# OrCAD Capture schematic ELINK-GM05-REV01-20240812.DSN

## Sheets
1 02 SIM: size A3; title: Elink-GM05-REV01; note: Main
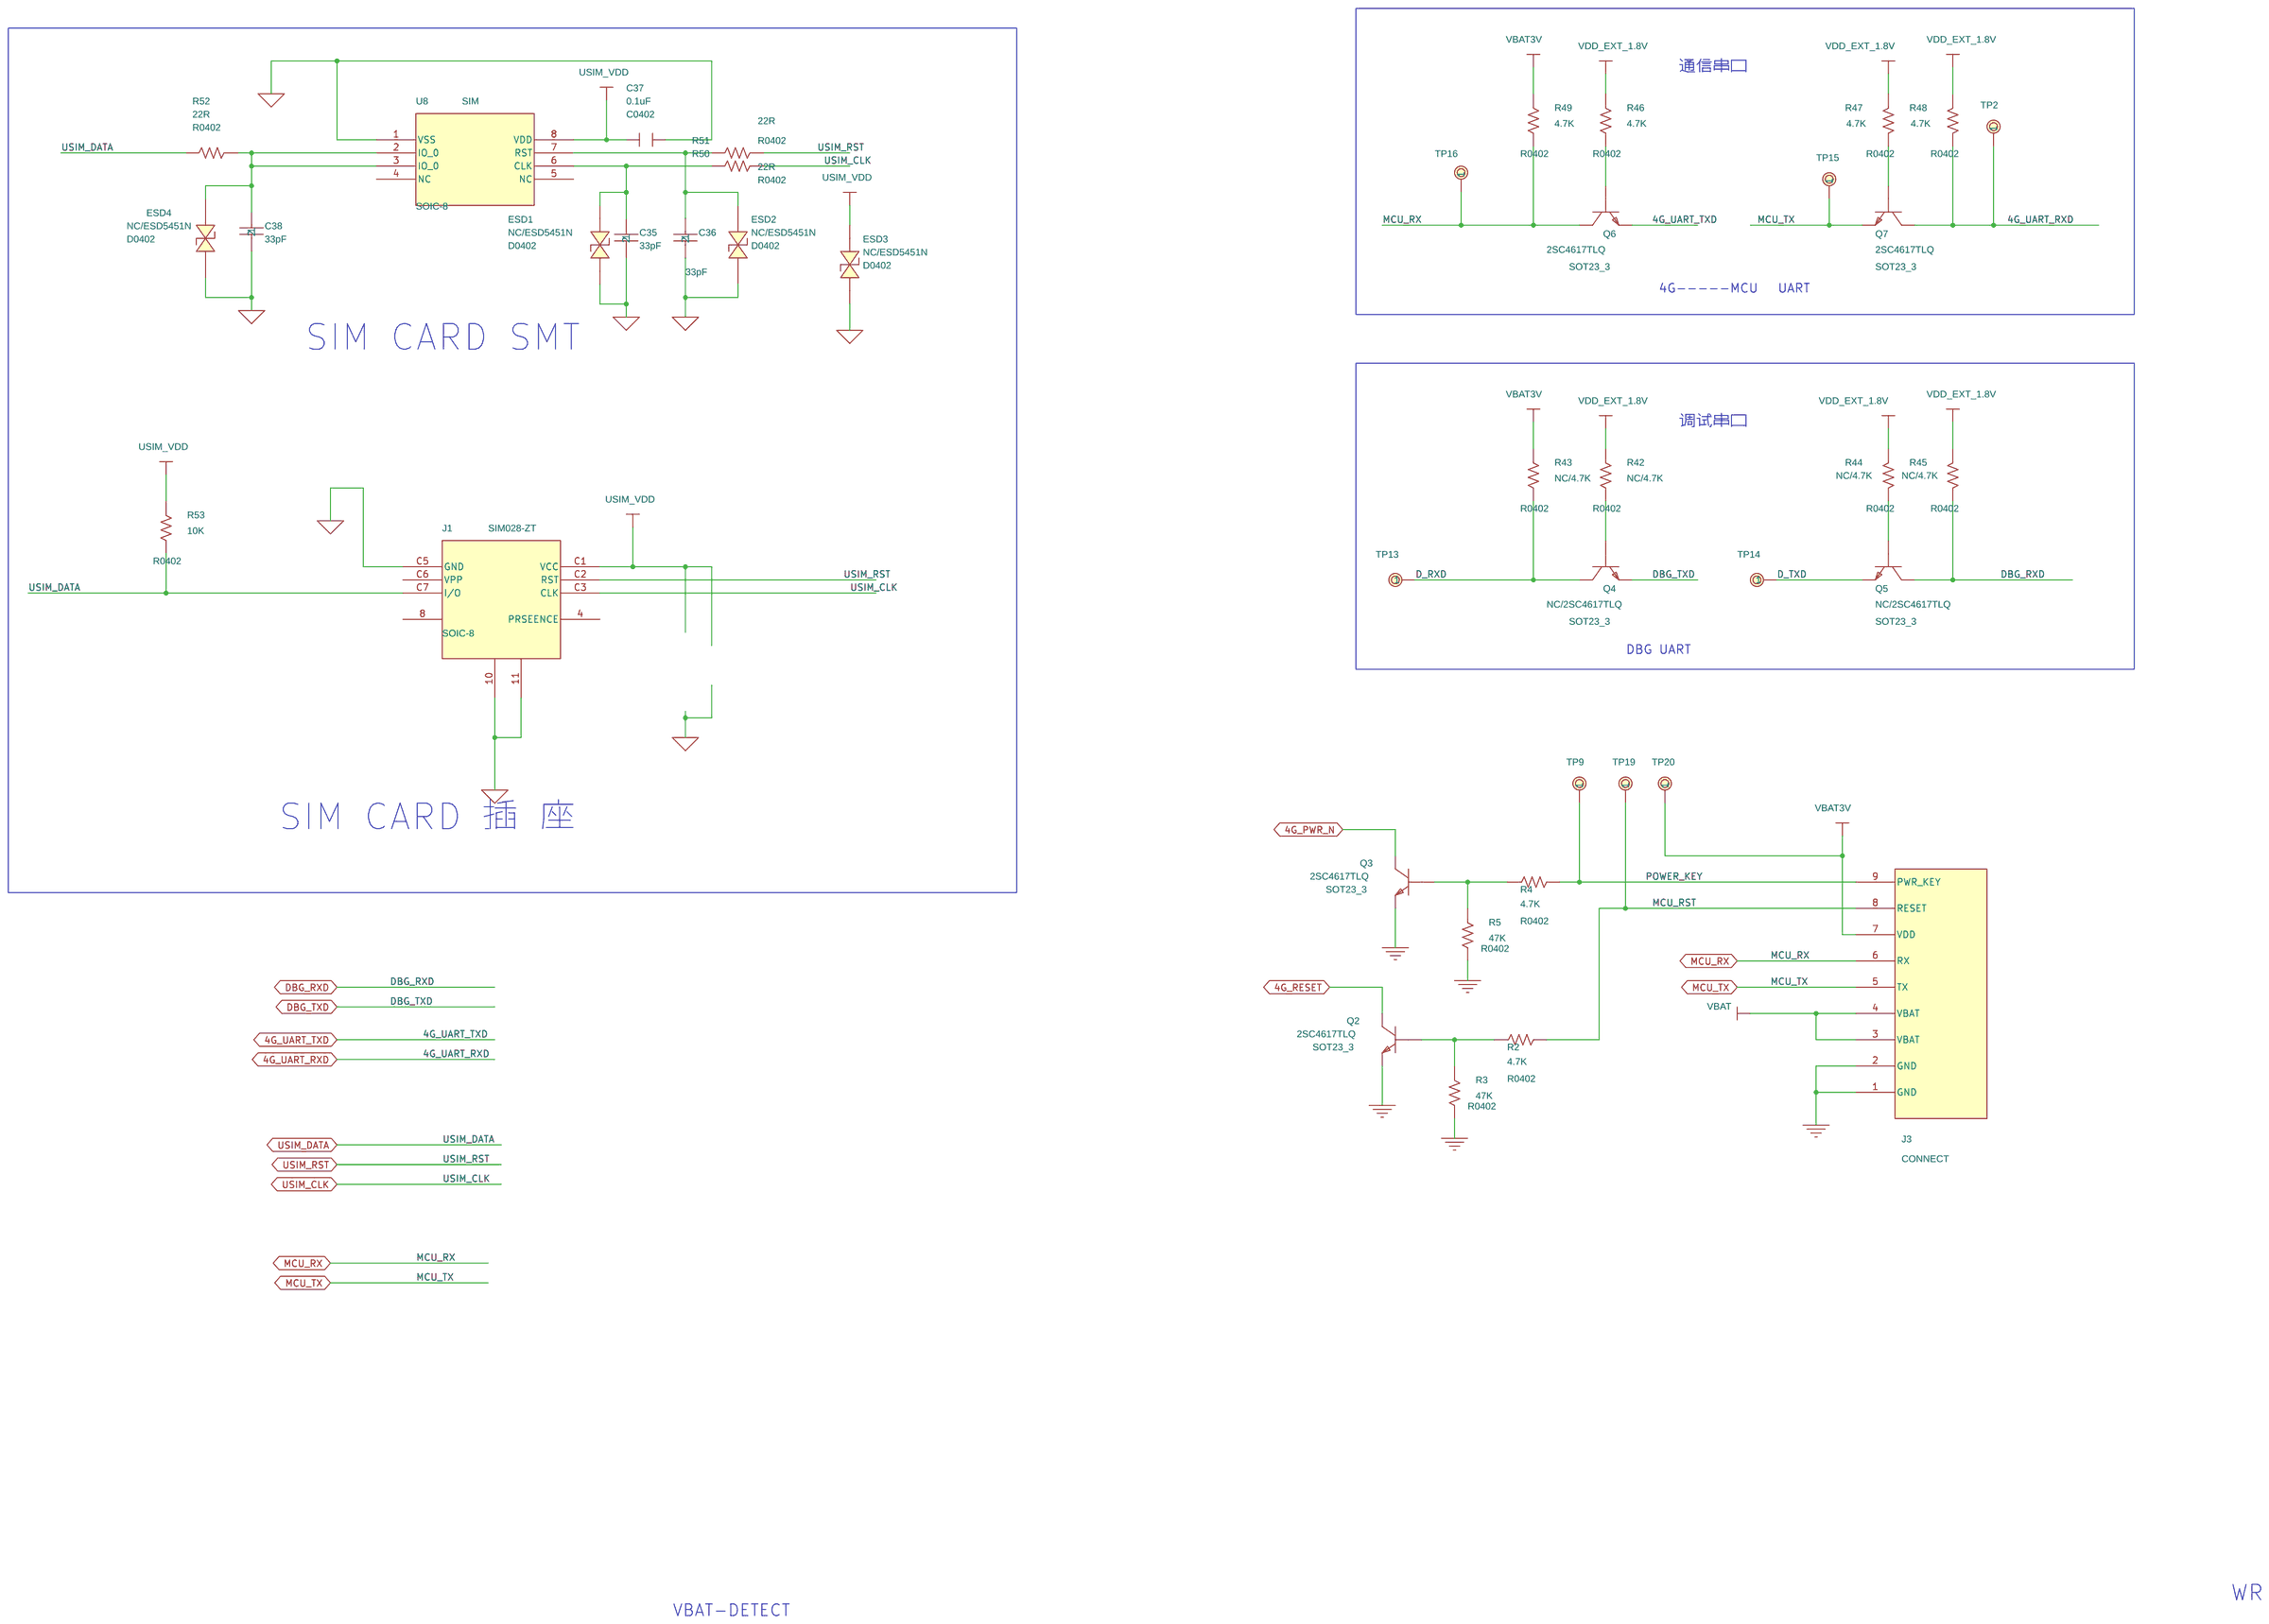
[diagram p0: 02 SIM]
2 01 4G: size A3; note: Power-Tree
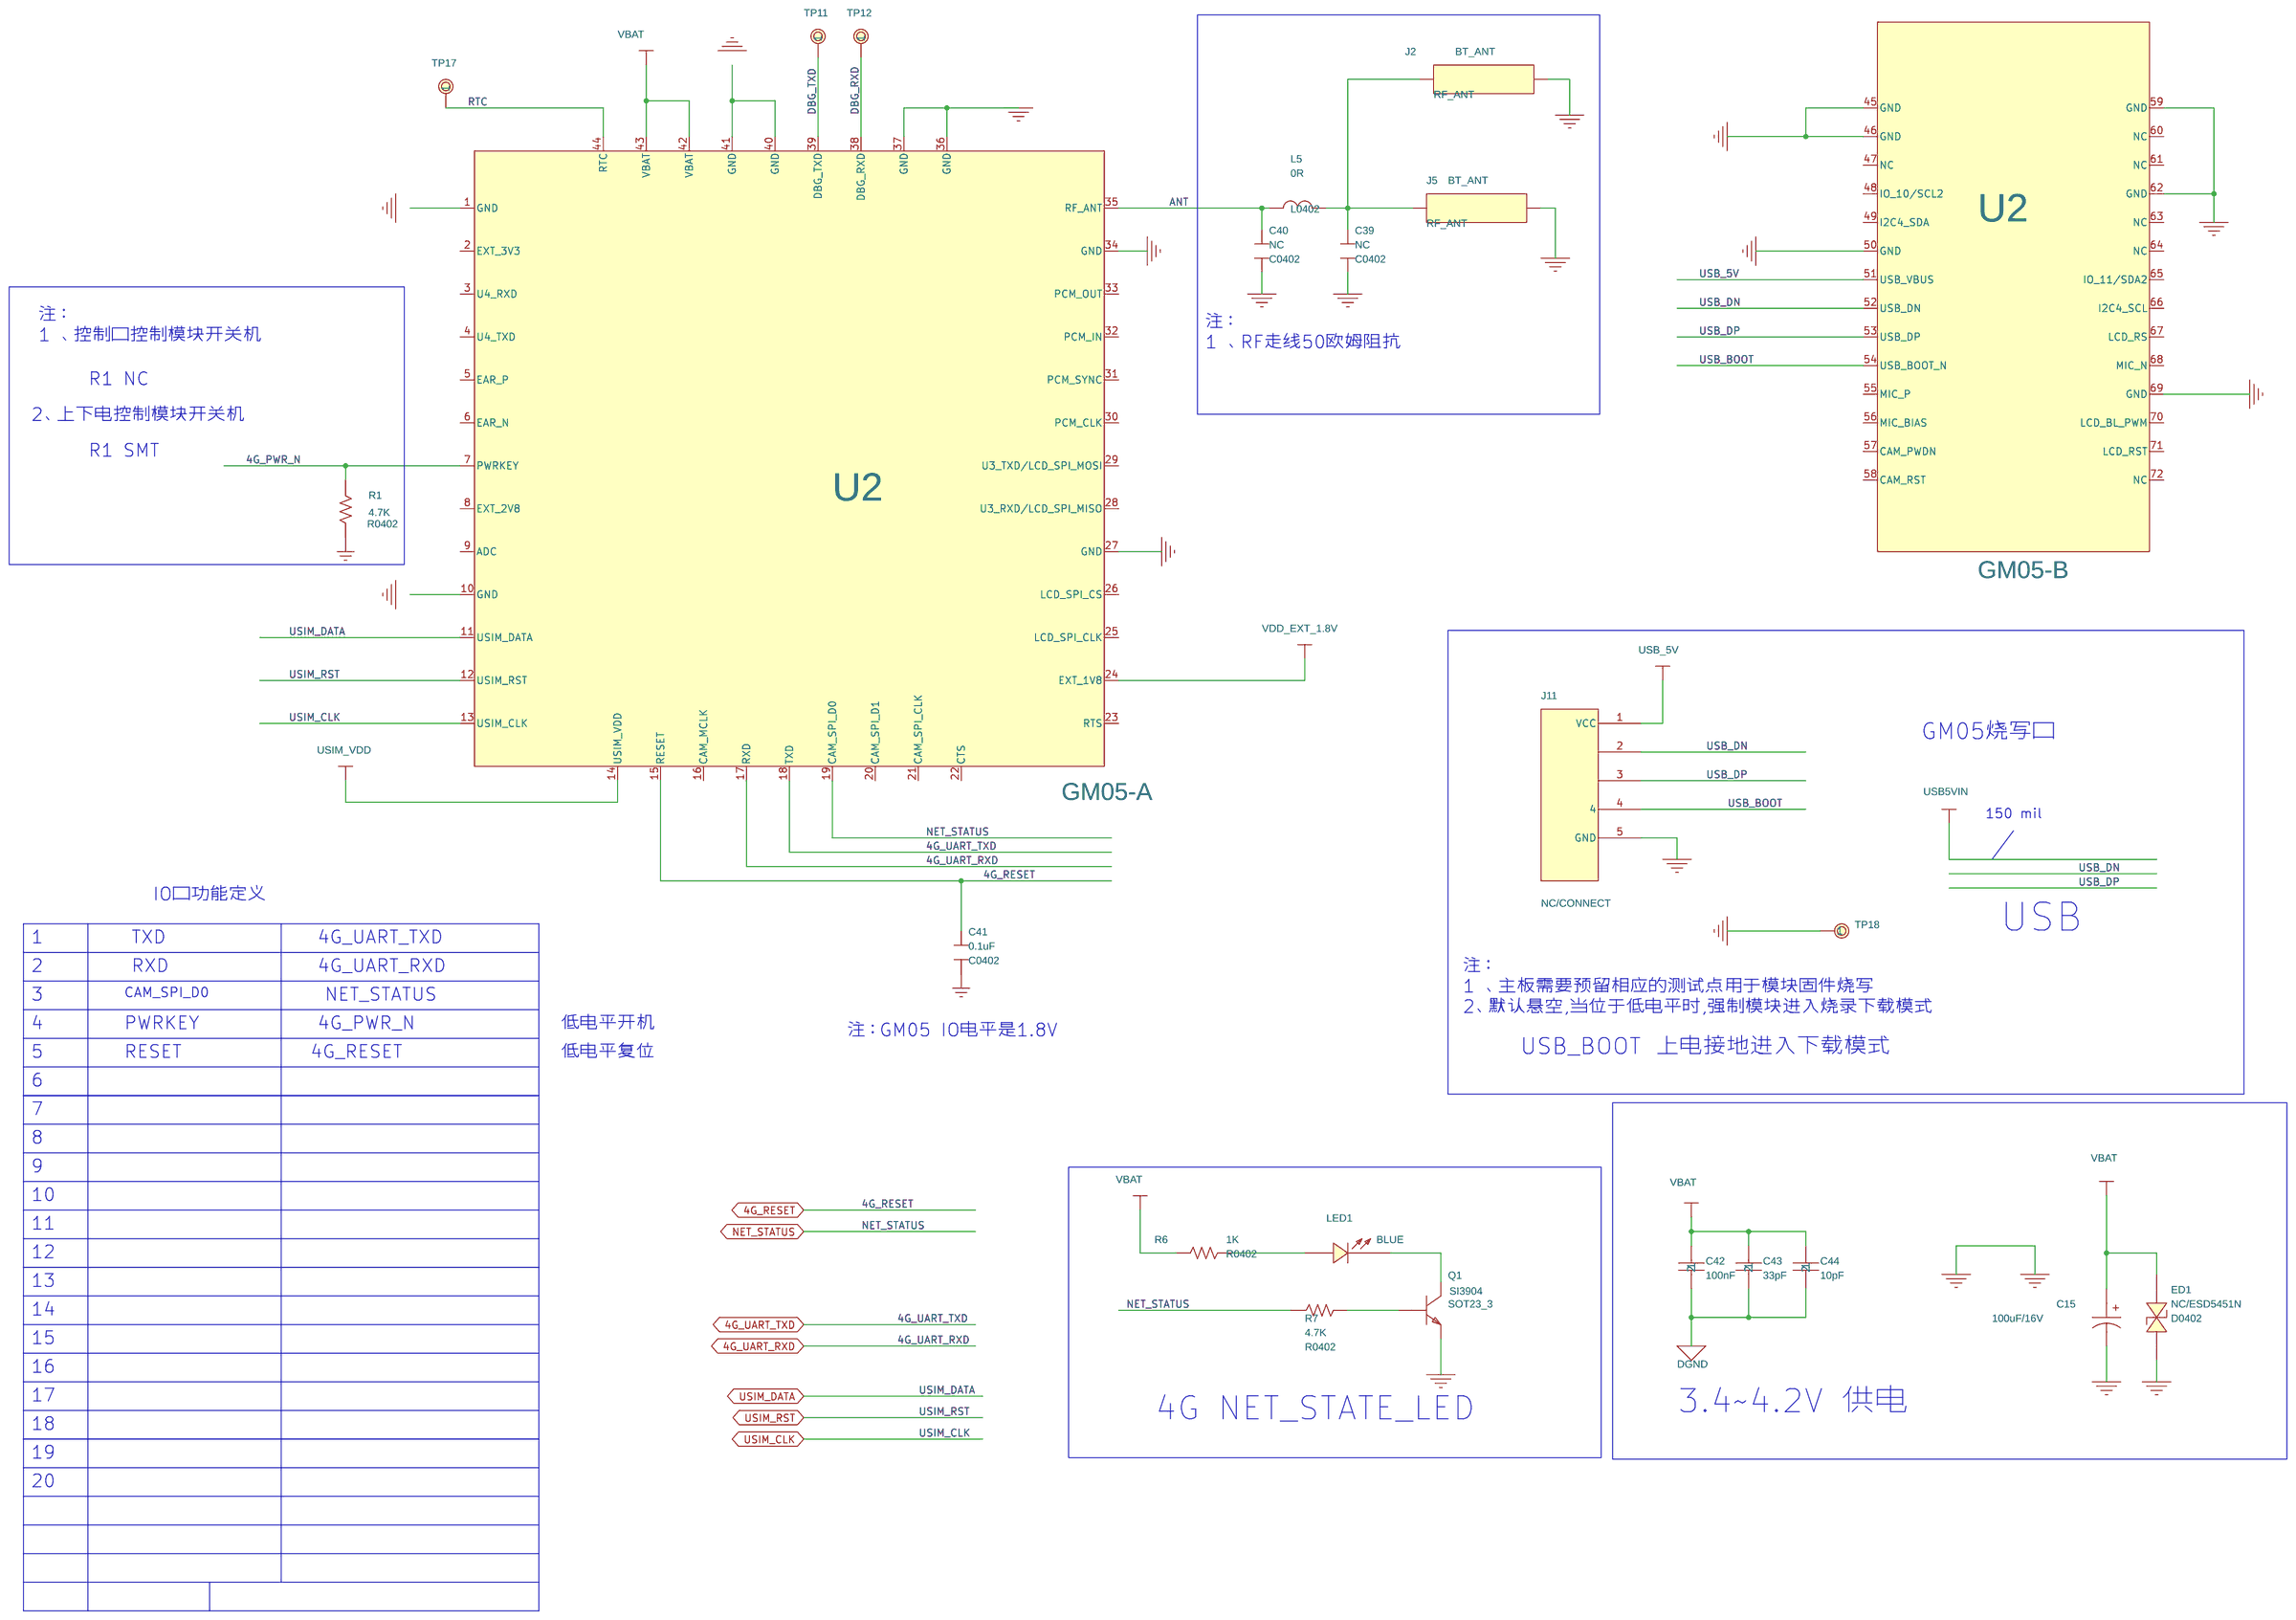
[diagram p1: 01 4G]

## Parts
sheet 01 4G
C15  100uF/16V
C39  NC  [C0402]
C40  NC  [C0402]
C41  0.1uF  [C0402]
C42  100nF  [0402m]
C43  33pF  [0402m]
C44  10pF  [0402m]
ED1  NC/ESD5451N  [D0402]
J2  BT_ANT  [RF_ANT]
J5  BT_ANT  [RF_ANT]
J11  NC/CONNECT  [MICROUSB-180-5P]
L5  0R  [L0402]
LED1  BLUE  [LED0603A]
Q1  SI3904  [SOT23_3]
R1  4.7K  [R0402]
R6  1K  [R0402]
R7  4.7K  [R0402]
TP11  TP  [TP50]
TP12  TP  [TP50]
TP17  TP  [TP50]
TP18  TP  [TP50]
U2  GM05-A  [aQFN60mp]
sheet 02 SIM
C35  33pF  [0402m]
C36  33pF  [0402m]
C37  0.1uF  [C0402]
C38  33pF  [0402m]
ESD1  NC/ESD5451N  [D0402]
ESD2  NC/ESD5451N  [D0402]
ESD3  NC/ESD5451N  [D0402]
ESD4  NC/ESD5451N  [D0402]
J1  SIM028-ZT  [SOIC-8]
J3  CONNECT  [MICROUSB-180-5P]
Q2  2SC4617TLQ  [SOT23_3]
Q3  2SC4617TLQ  [SOT23_3]
Q4  NC/2SC4617TLQ  [SOT23_3]
Q5  NC/2SC4617TLQ  [SOT23_3]
Q6  2SC4617TLQ  [SOT23_3]
Q7  2SC4617TLQ  [SOT23_3]
R2  4.7K  [R0402]
R3  47K  [R0402]
R4  4.7K  [R0402]
R5  47K  [R0402]
R42  NC/4.7K  [R0402]
R43  NC/4.7K  [R0402]
R44  NC/4.7K  [R0402]
R45  NC/4.7K  [R0402]
R46  4.7K  [R0402]
R47  4.7K  [R0402]
R48  4.7K  [R0402]
R49  4.7K  [R0402]
R50  22R  [R0402]
R51  22R  [R0402]
R52  22R  [R0402]
R53  10K  [R0402]
TP2  TP  [TP50]
TP9  TP  [TP50]
TP13  TP  [TP50]
TP14  TP  [TP50]
TP15  TP  [TP50]
TP16  TP  [TP50]
TP19  TP  [TP50]
TP20  TP  [TP50]
U8  SIM  [SOIC-8]

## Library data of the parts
C15 = CAPACITOR_POL_0
C39-C41 = CAPACITOR_0: PAGE: 1
C38 C42 = AVX_.01_uF_0603_2
C36 C43 = AVX_.01_uF_0603
C35 C44 = AVX_.01_uF_0603_1
ED1 ESD1-ESD4 = 1_1.5KE100A: 1ST PART DESCRIPTION: WILL ESD9B5V Bidirection ESD Protection
J2 J5 = FM_ANT_7
J11 = MINIUSB_13
L5 = INDUCTOR_2
LED1 = LED
Q1-Q7 = NPN_BEC
R1-R7 R42-R53 = R_v3
TP2 TP9 TP11-TP20 = TEST_POINT_SMD0.6: Test Pad; Unit Price: 0
U2 = DA14680_aQFN_5
C37 = CAPACITOR_1: PAGE: 1
J1 = BMA222_25
J3 = MINIUSB_17
U8 = BMA222_1

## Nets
DGND: C42.2 C43.2 C44.2
VBAT: C15.1 C42.1 C43.1 C44.1 ED1.2(CATHODE) J3.3(VBAT) J3.4(VBAT) R6.2 U2.42(VBAT) U2.43(VBAT)
VBAT3V: J3.7(VDD) R43.1 R49.1 TP20.1
VDD_EXT_1.8V: R42.1 R44.1 R45.1 R46.1 R47.1 R48.1 U2.24(EXT_1V8)
4G_PWR_N: R1.1 U2.7(PWRKEY)
4G_PWR_N (page 02 SIM): Q3.3(C)
4G_RESET: C41.2 Q2.3(C) U2.15(RESET)
4G_UART_RXD: Q7.3(C) R48.2 TP2.1 U2.17(RXD)
4G_UART_TXD: Q6.2(E) U2.18(TXD)
ANT: C40.2 L5.1 U2.35(RF_ANT)
CAM_MCLK: U2.16(CAM_MCLK)
CAM_SPI_CLK: U2.21(CAM_SPI_CLK)
CAM_SPI_D1: U2.20(CAM_SPI_D1)
CTS: U2.22(CTS)
D_RXD: Q4.3(C) R43.2 TP13.1
D_TXD: Q5.2(E) TP14.1
DBG_RXD: TP12.1 U2.38(DBG_RXD)
DBG_RXD (page 02 SIM): Q5.3(C) R45.2
DBG_TXD: TP11.1 U2.39(DBG_TXD)
DBG_TXD (page 02 SIM): Q4.2(E)
GGND: C15.2 C35.2 C36.2 C37.2 C38.2 C39.1 C40.1 C41.1 ED1.1(ANODE) ESD1.1(ANODE) ESD2.1(ANODE) ESD3.1(ANODE) ESD4.1(ANODE) J1.10 J1.11 J1.C5(GND) J2.2 J3.1(GND) J3.2(GND) J5.2 J11.5(GND) Q1.2(E) Q2.2(E) Q3.2(E) R1.2 R3.2 R5.2 TP18.1 U2.1(GND) U2.10(GND) U2.27(GND) U2.34(GND) U2.36(GND) U2.37(GND) U2.40(GND) U2.41(GND) U2.45(GND) U2.46(GND) U2.50(GND) U2.59(GND) U2.62(GND) U2.69(GND) U8.1(VSS)
MCU_RST: J3.8(RESET) R2.2 TP19.1
MCU_RX: J3.6(RX) Q6.3(C) R49.2 TP16.1
MCU_TX: J3.5(TX) Q7.2(E) TP15.1
NET_STATUS: R7.1 U2.19(CAM_SPI_D0)
POWER_KEY: J3.9(PWR_KEY) R4.2 TP9.1
RTC: TP17.1 U2.44(RTC)
USB_5V: J11.1(VCC) U2.51(USB_VBUS)
USB_BOOT: J11.4 U2.54(USB_BOOT_N)
USB_DN: J11.2 U2.52(USB_DN)
USB_DP: J11.3 U2.53(USB_DP)
USIM_CLK: J1.C3(CLK) R50.1 U2.13(USIM_CLK)
USIM_DATA: J1.C7(I/O) R52.2 R53.2 U2.11(USIM_DATA)
USIM_RST: J1.C2(RST) R51.1 U2.12(USIM_RST)
USIM_VDD: C37.1 ESD3.2(CATHODE) J1.C1(VCC) R53.1 U2.14(USIM_VDD) U8.8(VDD)
N29416450: C36.1 ESD2.2(CATHODE) R51.2 U8.7(RST)
N29416461: C35.1 ESD1.2(CATHODE) R50.2 U8.6(CLK)
N29416472: C38.1 ESD4.2(CATHODE) R52.1 U8.2(IO_0) U8.3(IO_0)
N29521520: C39.2 J2.1 J5.1 L5.2
N29552164: Q6.1(B) R46.2
N29552206: Q7.1(B) R47.2
N29561849: Q4.1(B) R42.2
N29561883: Q5.1(B) R44.2
N29581955: LED1.1(CATHODE) Q1.3(C)
N29581959: Q1.1(B) R7.2
N29581966: LED1.2(ANODE) R6.1
N29582813: Q2.1(B) R2.1 R3.1
N29584817: Q3.1(B) R4.1 R5.1

Not connected (* = marked no-connect by the designer): J1 4(PRSEENCE) 8 C6(VPP); U2 2(EXT_3V3) 3(U4_RXD) 4(U4_TXD) 5(EAR_P) 6(EAR_N) 8(EXT_2V8) 9(ADC) 23(RTS) 25(LCD_SPI_CLK) 26(LCD_SPI_CS) 28(U3_RXD/LCD_SPI_MISO) 29(U3_TXD/LCD_SPI_MOSI) 30(PCM_CLK) 31(PCM_SYNC) 32(PCM_IN) 33(PCM_OUT) 47(NC) 48(IO_10/SCL2) 49(I2C4_SDA) 55(MIC_P) 56(MIC_BIAS) 57(CAM_PWDN) 58(CAM_RST) 60(NC) 61(NC) 63(NC) 64(NC) 65(IO_11/SDA2) 66(I2C4_SCL) 67(LCD_RS) 68(MIC_N) 70(LCD_BL_PWM) 71(LCD_RST) 72(NC); U8 4(NC) 5(NC)

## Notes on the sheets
sheet 1
- 通信串口
- 4G-----MCU   UART
- SIM CARD SMT
- 调试串口
- DBG UART
- SIM CARD 插 座
- WR
- VBAT-DETECT
sheet 2
- 注：
  1 、控制口控制模块开关机
- 注：
  1 、RF走线50欧姆阻抗
- R1 NC
- 2、上下电控制模块开关机
- R1 SMT
- GM05烧写口
- 150 mil
- IO口功能定义
- USB
- 1
- TXD
- 4G_UART_TXD
- 2
- RXD
- 4G_UART_RXD
- 注：
  1 、主板需要预留相应的测试点用于模块固件烧写
  2、默认悬空,当位于低电平时,强制模块进入烧录下载模式
- 3
- CAM_SPI_D0
- NET_STATUS
- 4
- PWRKEY
- 4G_PWR_N
- 低电平开机
- 注：GM05 IO电平是1.8V
- USB_BOOT
- 上电接地进入下载模式
- 5
- RESET
- 4G_RESET
- 低电平复位
- 6
- 7
- 8
- 9
- 10
- 11
- 12
- 13
- 14
- 15
- 16
- 17
- 3.4~4.2V 供电
- 4G NET_STATE_LED
- 18
- 19
- 20
